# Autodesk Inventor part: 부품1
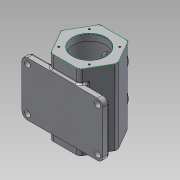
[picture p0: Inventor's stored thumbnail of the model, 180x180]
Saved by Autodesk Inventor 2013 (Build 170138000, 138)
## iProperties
Created: 2021-06
Part Number: 부품1
Material: 알루미늄 6061
Document SubType Name: Modeling
Designer: hana-max10
Mass: 1501.14 g
Surface Area: 1103.23 cm^2
Volume: 553.925 cm^3
Density: 2.71 g/cm^3
Author: hana-max10
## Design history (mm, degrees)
sketch "스케치1"
  geometry: L1 (26.25, 45.466)-(52.5, 0); L2 (52.5, 0)-(26.25, -45.466); L3 (26.25, -45.466)-(-26.25, -45.466); L4 (-26.25, -45.466)-(-52.5, 0); L5 (-52.5, 0)-(-26.25, 45.466); L6 (-26.25, 45.466)-(26.25, 45.466); L7 (-73.5, 0)-(73.5, 0) reference; L8 (0, -63.653)-(0, 63.653) reference; 2 further points
  constraints: 12 end point, 1 coincident, 1 perpendicular, 13 other
  dimensions: "d0" = 105 distance of L1.end L4.end
extrude "돌출1" new body sketch "스케치1" distance "d1" = 140; taper "d2" = 0 deg
node "작업 평면1"
sketch "스케치2"
  geometry: L1 (-75, -38)-(75, -38); L2 (75, -38)-(75, -50); L3 (75, -50)-(-75, -50); L4 (-75, -50)-(-75, -38); L5 (-73.5, 0)-(73.5, 0) reference; L6 (0, -68.459)-(0, 64.454) reference; 1 further point
  constraints: 8 end point, 2 parallel, 1 horizontal, 1 perpendicular, 1 other
  dimensions: "d4" = 12 distance of L1.end L2.end; "d6" = 50 distance between parallel lines of L3 L5; "d7" = 150 distance of L2.end L3.end
extrude "돌출2" join sketch "스케치2" distance "d8" = 45; taper "d9" = 0 deg; dims "d21" = 55, "d22" = 0
sketch "스케치3"
  geometry: L1 (0, 140)-(-45.466, 140) reference; L2 (0, 140)-(30, 140); L3 (37.5, 128)-(37.5, 12); L4 (30, 128)-(37.5, 128); L5 (30, 140)-(30, 128); L6 (30, 12)-(30, 0); L7 (37.5, 12)-(30, 12); L8 (0, 140)-(0, 0); L9 (0, 0)-(30, 0); L10 (0, 146.302)-(0, -28.105)
  constraints: 18 end point, 3 horizontal, 3 perpendicular, 2 point on line, 1 parallel, 1 vertical
  dimensions: "d13" = 30 distance of L2.start L2.end; "d15" = 12 distance of L2.end L4.start; "d16" = 12 distance of L6.start L6.end; "d17" = 116 distance of L3.start L3.end; "d18" = 37.5 distance between parallel lines of L8 L3; "d19" = 30 distance between parallel lines of L8 L6
revolve "회전1" sketch "스케치3" stored, may be unused: angle "d20" = 90 deg
sketch "스케치4"
  geometry: L1 (52.5, -140)-(0, -140) reference; L2 (52.5, 0)-(52.5, -140) reference; C1 r 20 at (26.25, -40); C2 r 20 at (26.25, -100); 1 further point
  constraints: 2 centre point
  dimensions: "d23" = 60 distance of C2.centre C1.centre; "d25" = 40 diameter of C1; "d26" = 40 diameter of C2; "d27" = 26.25 distance from line of L2 C2.centre; "d28" = 26.25 distance from line of L2 C1.centre; "d29" = 40 distance from line of L1 C2.centre
extrude "돌출3" join sketch "스케치4" distance "d30" = 7.034; taper "d31" = 0 deg
sketch "스케치5"
  geometry: L1 (26.25, 40)-(26.25, -100) reference; C1 r 20 at (0, 0) reference; 3 further points
  constraints: 1 coincident
  dimensions: "d32" = 60 distance of point (0, 0) point (0, -60); "d34" = 26.25 distance from line of L1 point (0, -60)
hole "구멍1" sketch "스케치5" at (0, 0), (0, -60) diameter "d35" = 25; stored, may be unused: countersink angle "d39" = 90 deg, drill point angle "d41" = 0 deg; dims "d36" = 6, "d37" = 30, "d38" = 8, "d40" = 20
sketch "스케치6"
  geometry: L1 (52.5, 0)-(26.25, 45.466) reference; L2 (26.25, 45.466)-(-26.25, 45.466) reference; L3 (-26.25, 45.466)-(-52.5, 0) reference; L4 (-52.5, 0)-(-26.25, -45.466) reference; L5 (-26.25, -45.466)-(26.25, -45.466) reference; L6 (26.25, -45.466)-(52.5, 0) reference; C1 r 30 at (0, 0) reference
sketch "스케치7"
  geometry: C1 r 30 at (0, 0) reference; A1 r 40 centre (0, 0) between (0, 40) and (40, 0); 2 further points
  constraints: 4 point on circle, 1 centre point, 1 coincident
  dimensions: "d42" = 80 diameter of A1
hole "구멍2" sketch "스케치7" at (0, 40), (40, 0), (0, -40), (-40, 0) diameter "d44" = 3.242; stored, may be unused: countersink angle "d48" = 90 deg, drill point angle "d50" = 118 deg; dims "d45" = 8, "d46" = 30, "d47" = 8, "d49" = 10
sketch "스케치8"
  geometry: L1 (0, 0)-(-47.315, 47.315); L2 (-105, 0)-(105, 0) reference; L3 (0, -70.5)-(0, 73) reference; L4 (0, 0)-(52.5, 52.5); L5 (0, 0)-(38.7, -38.7); L6 (0, 0)-(-44.373, -44.373); C1 r 30 at (0, 0) reference; A1 r 40 centre (0, 0) between (-28.284, 28.284) and (-28.284, -28.284); 2 further points
  constraints: 8 end point, 4 point on circle, 4 point on line, 1 centre point, 1 coincident, 1 perpendicular
  dimensions: "d51" = 80 diameter of A1; "d52" = 45 deg angle of L3 L1; "d55" = 45 deg angle of L2 L5; "d57" = 45 deg angle of L3 L6
hole "구멍3" sketch "스케치8" at (-28.284, -28.284), (-28.284, 28.284), (28.284, 28.284), (28.284, -28.284) diameter "d59" = 3.242; stored, may be unused: countersink angle "d63" = 90 deg, drill point angle "d65" = 118 deg; dims "d60" = 8, "d61" = 30, "d62" = 8, "d64" = 10
fillet "모깎기1" dims "d66" = 10
sketch "스케치9"
  geometry: C1 r 5.5 at (-95.561, 90); C2 r 5.5 at (34.439, 10); C3 r 5.5 at (-95.561, 10); C4 r 5.5 at (34.439, 90); A1 r 10 centre (34.439, 90) between (44.439, 90) and (34.439, 100) reference; A2 r 10 centre (34.439, 10) between (34.439, 0) and (44.439, 10) reference; A3 r 10 centre (-95.561, 90) between (-95.561, 100) and (-105.561, 90) reference; A4 r 10 centre (-95.561, 10) between (-105.561, 10) and (-95.561, 0) reference; 1 further point
  constraints: 4 centre point, 4 concentric
  dimensions: "d67" = 11 diameter of C1; "d69" = 11 diameter of C4; "d70" = 11 diameter of C2; "d71" = 11 diameter of C3
extrude "돌출4" cut sketch "스케치9" distance "d72" = 12; taper "d73" = 0 deg
sketch "스케치10"
  geometry: L1 (0, 0)-(-34.439, 0) reference; L2 (-44.439, 90)-(-44.439, 10) reference; 2 further points
  constraints: 1 other
  dimensions: "d74" = 14 distance from line of L2 point (-30.439, 50); "d75" = 50 distance from line of L1 point (-30.439, 50)
feature "엠보싱1" sketch "스케치10" dims "d0" = 105, "d76" = 0.5, "d77" = 0
fillet "모깎기2" dims "d78" = 8
fillet "모깎기3" dims "d79" = 5
chamfer "모따기1" distance "d80" = 1; stored, may be unused: second distance "d81" = 2, angle "d82" = 45 deg
fillet "모깎기4" dims "d83" = 3
fillet "모깎기5" dims "d84" = 3
fillet "모깎기6" dims "d85" = 3
node "솔리드1"
